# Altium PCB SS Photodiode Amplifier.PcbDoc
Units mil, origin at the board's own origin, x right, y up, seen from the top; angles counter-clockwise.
Board outline 2000 x 1500 mil, 2 copper layers (Top Layer, Bottom Layer), stack 62 mil thick; 19 components, 6 nets, 62 pads, 2 vias.
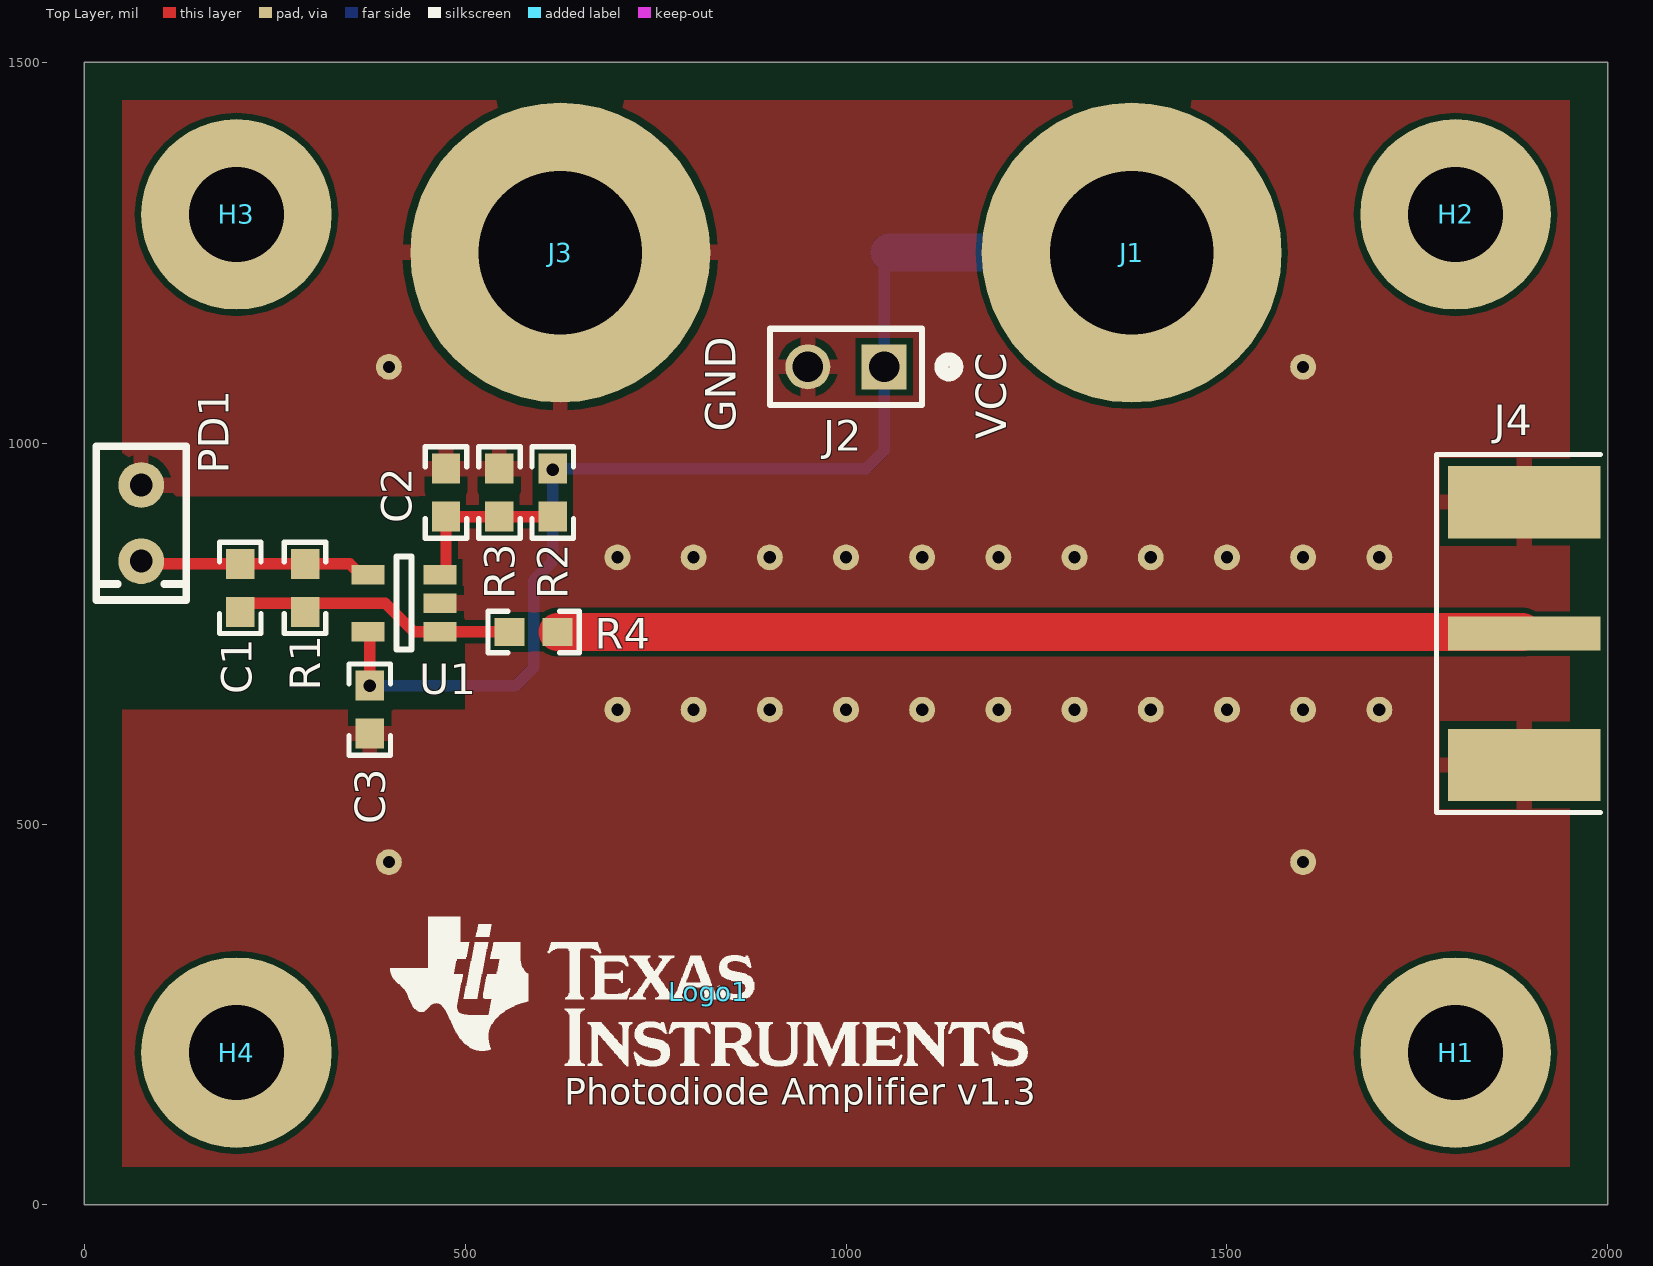
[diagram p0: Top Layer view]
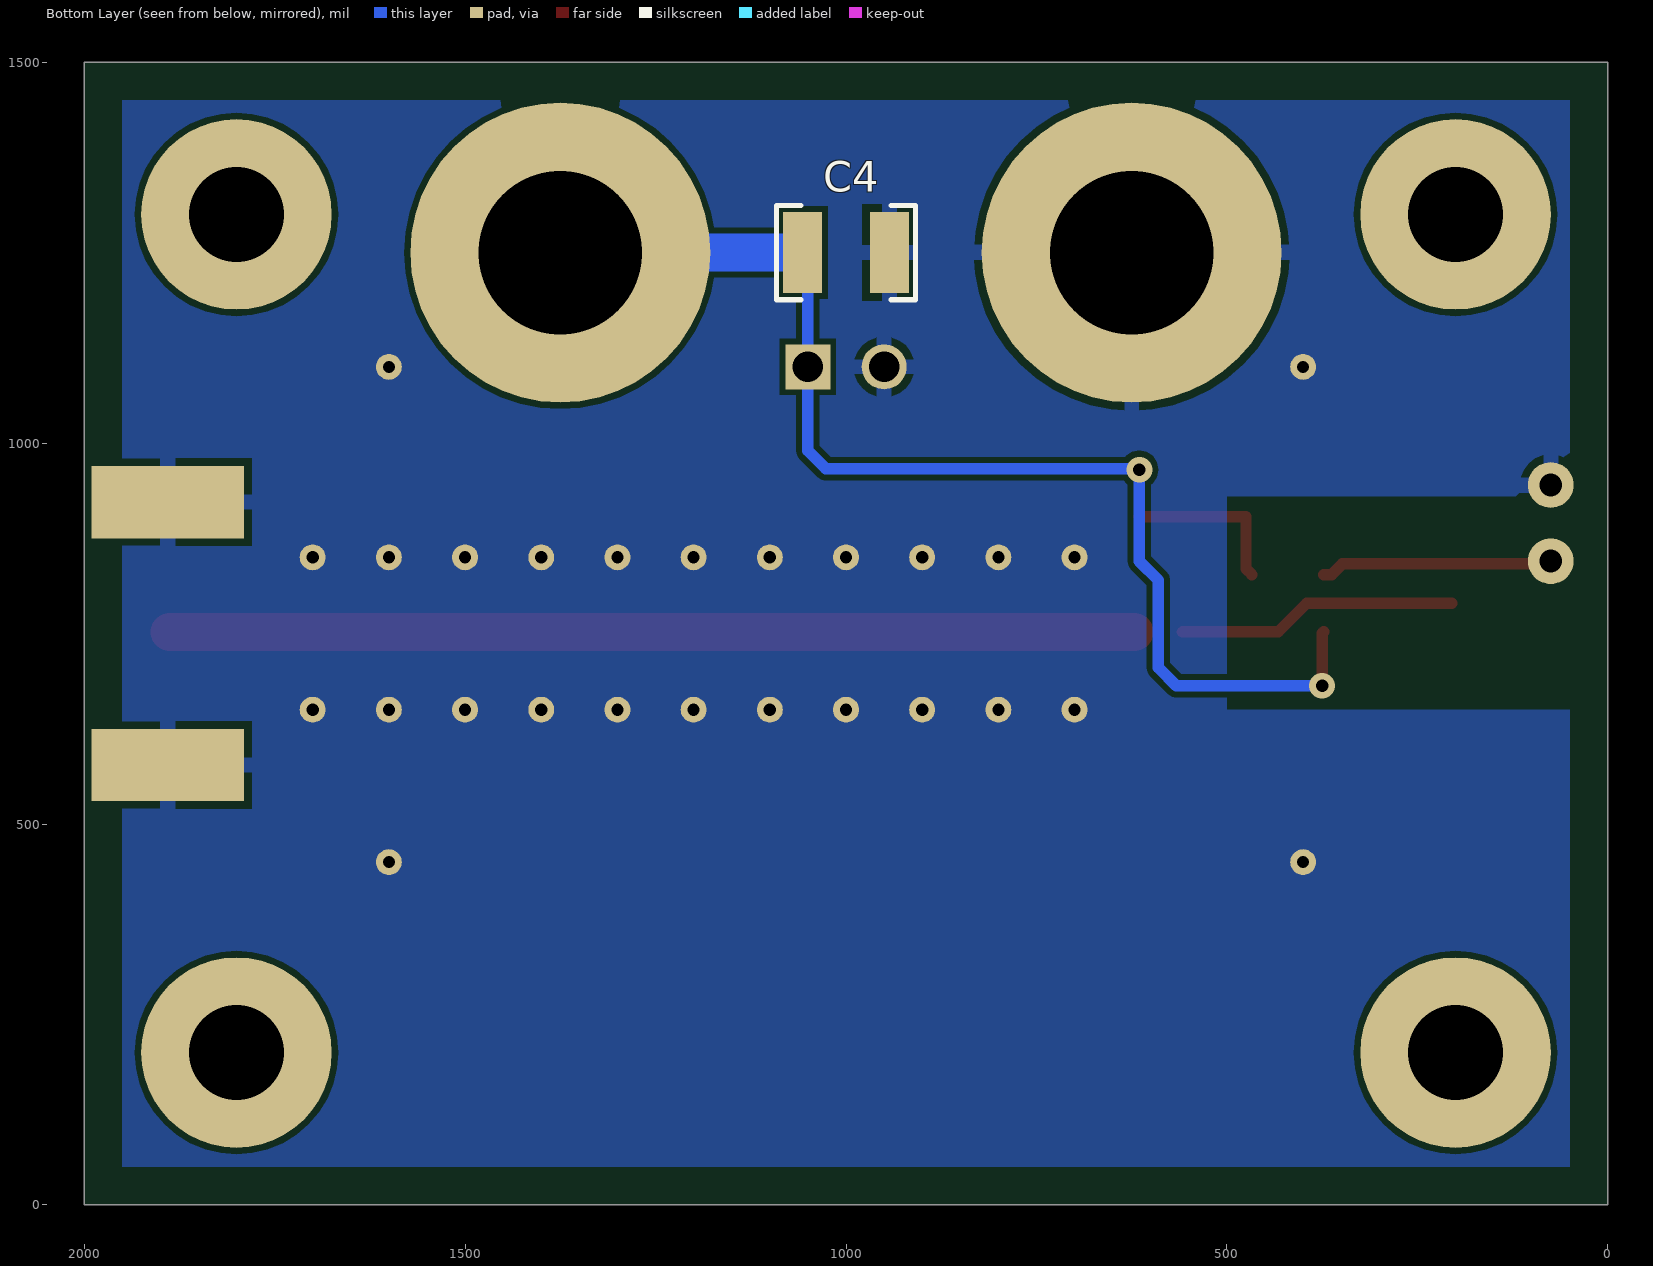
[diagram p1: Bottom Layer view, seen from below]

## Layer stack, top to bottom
Top Layer: signal copper 1.4
Dielectric: core 59.2, FR-4, Dk 4.8
Bottom Layer: signal copper 1.4

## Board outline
0,0 2000,0 2000,1500 0,1500

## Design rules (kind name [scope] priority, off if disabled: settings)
AcuteAngle [All] p1: minimum=4.50000000000000E+0001 checktracksonly=FALSE
AssemblyTestPointUsage [All] p1: valid=2
Clearance "Transmission Line Clearance" [InNet('NetJ4_1')] p1: gap=7
Clearance Clearance_BoardEdge_MountingHoles [OnCopper and InComponentClass('Mounting Holes') vs IsKeepOut] p2: gap=40
Clearance Clearance_BoardEdge_Poly [OnCopper and InPoly vs IsKeepOut] p3: gap=25
Clearance Clearance_BoardEdge [OnCopper and Not InComponentClass('Logo') and not InComponentClass('FiducialMark') and not InRegion(1000,500,4000,800) vs IsKeepOut] p4: gap=75
Clearance [All] p5: gap=8
ComponentClearance ComponentClearance_Logo [InComponentClass(Logo)] p1: gap=50 collisioncheckmode=3 verticalgap=10 showdistances=FALSE
ComponentClearance ComponentClearance_ScrewToNut [(HasFootprint('NY PMS 440 0025 PH')) vs (HasFootprint('Keystone_1902C'))] p2: gap=5 collisioncheckmode=3 verticalgap=10 showdistances=FALSE
ComponentClearance ComponentClearance_MountingHoles [InComponentClass('Mounting Holes')] p3: gap=250 collisioncheckmode=3 verticalgap=100000 showdistances=FALSE
ComponentClearance ComponentClearance_SmallPassives [HasFootprint('0201*') or HasFootprint('0402*') or HasFootprint('0508') or HasFootprint('0603*') or HasFootprint('0612') or HasFootprint('0805*') or HasFootprint('0815*') or HasFootprint('0830*') or HasFootprint('1206*') or HasFootprint('1210*') or HasFootprint('1808*') or HasFootprint('1812*') or HasFootprint('1825*') or HasFootprint('2010*') or HasFootprint('2220*') or HasFootprint('2225*') or HasFootprint('2512*') or HasFootprint('2728*') or HasFootprint('3518*') vs HasFootprint('0201*') or HasFootprint('0402*') or HasFootprint('0508') or HasFootprint('0603*') or HasFootprint('0612') or HasFootprint('0805*') or HasFootprint('0815*') or HasFootprint('0830*') or HasFootprint('1206*') or HasFootprint('1210*') or HasFootprint('1808*') or HasFootprint('1812*') or HasFootprint('1825*') or HasFootprint('2010*') or HasFootprint('2220*') or HasFootprint('2225*') or HasFootprint('2512*') or HasFootprint('2728*') or HasFootprint('3518*')] p4: gap=10 collisioncheckmode=3 verticalgap=10 showdistances=FALSE
ComponentClearance ComponentClearance_THtoSMT [IsThruComponent vs IsSMTComponent] p5: gap=10 collisioncheckmode=3 verticalgap=100000 showdistances=FALSE
ComponentClearance ComponentClearance_THtoTH [IsThruComponent vs IsThruComponent] p6: gap=10 collisioncheckmode=3 verticalgap=100000 showdistances=FALSE
ComponentClearance [All] p7: gap=40 collisioncheckmode=3 verticalgap=10 showdistances=FALSE
DiffPairsRouting [All] p1: maxlimit=100 minlimit=10 mostfreqgap=10 maxuncoupledlength=1000
FabricationTestPointUsage TestPointUsage [All] p1: valid=2 allowmultiple=FALSE
FabricationTestpoint Testpoint [All] p1: side=3 testpointundercomponent=TRUE minsize=40 maxsize=100 preferedsize=60 minholesize=0 maxholesize=40 preferedholesize=32 testpointgrid=1 allowsidetop=TRUE allowsidebottom=TRUE usegrid=TRUE gridtolerance=0.01
FanoutControl Fanout_LCC [IsLCC] p1: bgadir=Out bgaviamode=Centered fanoutstyle=Auto fanoutdirection=Alternating viagrid=1 // Fanout_LCC (Default Rule)
FanoutControl Fanout_BGA [IsBGA] p2: bgadir=Out bgaviamode=Centered fanoutstyle=Auto fanoutdirection=Alternating viagrid=1 // Fanout_BGA (Default Rule)
FanoutControl Fanout_Default [All] p4: bgadir=Out bgaviamode=Centered fanoutstyle=Auto fanoutdirection=Alternating viagrid=1 // Fanout_Default (Default Rule)
FanoutControl Fanout_Small [(CompPinCount < 5)] p5: bgadir=Out bgaviamode=Centered fanoutstyle=Auto fanoutdirection=OutThenIn viagrid=1 // Fanout_Small (Default Rule)
HoleSize [All] p1: absolutevalues=TRUE maxlimit=251 minlimit=8 maxpercent=80.000 minpercent=20.000
MinimumAnnularRing [All] p1: minimumring=9
MinimumSolderMaskSliver MinimumSolderMaskSliver_Logo [InComponentClass('Logo') vs InComponentClass('Logo')] p1: minsoldermaskwidth=0.7
MinimumSolderMaskSliver [All] p2: minsoldermaskwidth=4
PlaneConnect [All] p1: planeconnectstyle=Relief reliefexpansion=10 reliefentries=4 reliefconductorwidth=10 reliefairgap=10
PolygonConnect GNDVia [InPadClass('GNDVia')] p1: connectstyle=Direct reliefconductorwidth=10 reliefentries=4 polygonreliefangle="90 Angle" airgapwidth=10
PolygonConnect "SMA GND" [(InComponent('J1') AND InNet('GND'))] p2: connectstyle=Direct reliefconductorwidth=10 reliefentries=4 polygonreliefangle="90 Angle" airgapwidth=10
PolygonConnect [All] p3: connectstyle=Relief reliefconductorwidth=20 reliefentries=4 polygonreliefangle="90 Angle" airgapwidth=10
RoutingVias [All] p1: holewidth=16 width=34 viastyle="Through Hole" minholewidth=8 minwidth=26 maxholewidth=40 maxwidth=65
SMDToCorner [All] p1: distance=30000
SilkToSilkClearance [All] p1: silktosilkclearance=5
SilkscreenOverComponentPads [All] p1: minsilkscreentomaskgap=5
SolderMaskExpansion [All] p1: expansion=3
Width [All] p1: maxlimit=100 minlimit=6 preferedwidth=15 checkconnectedcopper=TRUE
14 further rules are at their usual default settings.

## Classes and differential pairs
component class Logo: Logo1
component class Header: J2
component class Schematic: C1 C2 C3 H1 H2 H3 H4 J1 J2 J3 Logo1 PD1 R1 R2 R3 R4 U1
pad class GNDVia: Free-0 Free-1 Free-2 Free-3 Free-4 Free-5 Free-6 Free-7 Free-8 Free-9 Free-10 Free-11 Free-12 Free-13 Free-14 Free-15 Free-16 Free-17 Free-18 Free-19 Free-20 Free-21 Free-22 Free-23 Free-24 Free-25

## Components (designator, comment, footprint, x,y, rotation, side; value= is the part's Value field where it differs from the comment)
C1 "06035A2R7CAT2A" 0603 205,810 r90 top
C2 "C0603C105K4PACTU" 0603 475,935 r90 top
C3 "0603YC104JAT2A" 0603 375,650 r90 top
C4 "C1210C106K8PACTU" 1210 1000,1250 r180 bottom
H1 "NA" "Mounting Hole" 1800,200 r0 top
H2 "NA" "Mounting Hole" 1800,1300 r0 top
H3 "NA" "Mounting Hole" 200,1300 r0 top
H4 "NA" "Mounting Hole" 200,200 r0 top
J1 "575-4" Keystone_575-4 1375,1250 r0 top
J2 "5-146261-1" CONN_5-146261-1 1000,1100 r180 top
J3 "575-4" Keystone_575-4 625,1250 r180 top
J4 "142-0701-851" Emerson_142-0701-851 1890,750 r270 top
Logo1 "Texas Instruments" TI_Stacked_Overlay_Small 820,280 r0 top
PD1 "PDB-C156" PDB-C156 75,895 r180 top
R1 "CRCW060353K6FKEA" 0603 290,810 r270 top
R2 "CRCW060310K0FKEA" 0603 615,935 r270 top
R3 "CRCW0603205RFKEA" 0603 545,935 r270 top
R4 "CRCW060349R9FKEA" 0603 590,752 r0 top
U1 "OPA322AIDBVR" DBV0005A_N 420,790 r180 top

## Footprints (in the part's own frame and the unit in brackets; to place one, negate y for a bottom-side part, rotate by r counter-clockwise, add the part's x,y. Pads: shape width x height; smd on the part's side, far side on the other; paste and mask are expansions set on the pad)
0603 [mm] "0603 from SM-752 data"
  rect 1x0.95 smd: 1(-0.8,0) 2(0.8,0)
  silkscreen extent -1.52,-0.69 1.52,0.69, body extent -0.87,-0.47 0.87,0.47, height 0.85
1210 [mm] "1210 from SM-752 data"
  rect 1.3x2.7 smd: 1(-1.45,0) 2(1.45,0)
  silkscreen extent -2.32,-1.57 2.32,1.57, body extent -1.7,-1.35 1.7,1.35, height 1.35
CONN_5-146261-1 [mm] "Sullins"
  rect 1.5x1.5 hole 1.02: 1(-1.27,0)
  round 1.5 hole 1.02: 2(1.27,0)
  silkscreen extent -3.68,-1.27 2.54,1.27, body extent -2.51,-1.27 2.51,1.27, height 10.87
DBV0005A_N [mm] "SOT23, 5-Leads, Body 2.9x1.6mm, Pitch 0.95mm, Lead Span 2.8mm, IPC Medium Density"
  rect 1.1x0.65 smd: 1(-1.2,0.95) 2(-1.2,0) 3(-1.2,-0.95) 4(1.2,-0.95) 5(1.2,0.95)
  silkscreen extent -0.25,-1.55 0.25,1.55, body extent -1.42,-1.46 1.42,1.46, height 1.08
Emerson_142-0701-851 [mil] "Johnson Components"
  rect 45x200 smd: 1(0,0)
  rect 95x200 smd: 2(-172.5,0) 3(172.5,0)
  rect 95x200 smd far side: 4(172.5,0) 5(-172.5,0)
  silkscreen extent -235,-115 235,100, body extent -190,-95 190,487, height 155
Keystone_575-4 [mm] "Banana Jack"
  round 10 hole 5.45: 1(0,0)
  body extent -3.95,-3.95 3.92,3.93, height 2.36
"Mounting Hole" [mil]
  round 250 hole 125: 1(0,0)
PDB-C156 [mil] "Photodiode"
  round 60 hole 30: 1(0,50) 2(0,-50)
  silkscreen extent -59,-101 59,101
TI_Stacked_Overlay_Small [mil]
  silkscreen extent -418,-98 418,98

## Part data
C1: "CAP, CERM, 2.7pF, 50V, +/-9%, C0G/NP0, 0603"
C2: "CAP, CERM, 1uF, 16V, +/-10%, X5R, 0603"
C3: "CAP, CERM, 0.1uF, 16V, +/-5%, X7R, 0603"
C4: "CAP, CERM, 10uF, 10V, +/-10%, X5R, 1210"
H1 H2 H3 H4: library part "Mounting Hole", "Mounting Hole"
J1 J3: "Standard Banana Jack, Uninsulated, 5.5mm"
J2: "Header, 100mil, 2x1, Gold, TH"
J4: "Connector, SMT, End launch SMA 50 ohm"
Logo1: library part TI_Logo, "Texas Instrument Corporate Signature"
PD1: "Photodiode"
R1: "RES, 53.6k ohm, 1%, 0.1W, 0603"
R2: "RES, 10.0k ohm, 1%, 0.1W, 0603"
R3: "RES, 205 ohm, 1%, 0.1W, 0603"
R4: "RES, 49.9 ohm, 1%, 0.1W, 0603"
U1: "20 MHz, Low Noise, RRIO, CMOS Operational Amplifier with Shutdown, 1.8 to 5.5 V, -40 to 125 degC, 5-pin SOT23 (DBV0005A), Green (RoHS & no Sb/Br)"

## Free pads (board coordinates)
  round 34 hole 16: 0(700,850) 1(800,850) 2(900,850) 3(1000,850) 4(1100,850) 5(1200,850) 6(1300,850) 7(1400,850) 8(1500,850) 9(1600,850) 10(1700,850) 11(1700,650) 12(1600,650) 13(1500,650) 14(1400,650) 15(1300,650) 16(1200,650) 17(1100,650) 18(1000,650) 19(900,650) 20(800,650) 21(700,650) 22(400,1100) 23(400,450) 24(1600,450) 25(1600,1100)

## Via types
v1: diameter 34, hole 16, Top Layer to Bottom Layer, 2 vias

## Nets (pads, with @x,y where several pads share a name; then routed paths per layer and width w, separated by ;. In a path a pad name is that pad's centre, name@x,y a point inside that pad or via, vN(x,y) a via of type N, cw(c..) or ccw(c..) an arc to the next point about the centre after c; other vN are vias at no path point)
GND: C2.2 C3.1 C4.2 J2.2 J3.1 J4.2 J4.3 J4.4 J4.5 pad.0 pad.1 pad.2 pad.3 pad.4 pad.5 pad.6 pad.7 pad.8 pad.9 pad.10 pad.11 pad.12 pad.13 pad.14 pad.15 pad.16 pad.17 pad.18 pad.19 pad.20 pad.21 pad.22 pad.23 pad.24 pad.25 PD1.2 R3.1 U1.2
NetC1_1: C1.1 R1.2 R4.1 U1.1 | length 369.2
  Top Layer w15: C1.1@205,790 395,790 432.4,752.6 U1.1 557.91,752.6 R4.1
NetC1_2: C1.2 PD1.1 R1.1 U1.4 | length 299.2
  Top Layer w15: PD1.1@80,840 81.5,841.5 R1.1 348.5,841.5 362.6,827.4 U1.4
NetC2_1: C2.1 R2.2 R3.2 U1.3 | length 219.3
  Top Layer w15: U1.3 475,835.16 C2.1 R2.2
NetJ4_1: J4.1 R4.2 | length 1269.3
  Top Layer w15: J4.1@1888,752 J4.1
  Top Layer w50: R4.2 J4.1@1888,752
VCC: C3.2 C4.1 J1.1 J2.1 R2.1 U1.5 | length 1594.2
  Top Layer w15: U1.5 375,750.35 v1(375,681.5)
  Bottom Layer w15: v1(375,681.5) 566.5,681.5 590,705 590,820 615,845 615,966.5 1026.5,966.5 1050,990 J2.1 1050,1242.91 C4.1
  Bottom Layer w50: C4.1 J1.1
  other v1: 615,965
pads on no net: H1.1 H2.1 H3.1 H4.1

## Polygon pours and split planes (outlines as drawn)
GND on Top Layer "Top Layer GND" (solid, pour order 4): 50,1450 50,50 1950,50 1950,1450
GND on Bottom Layer "Bottom Layer GND" (solid, pour order 3): 50,1450 50,50 1950,50 1950,1450

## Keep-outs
Keep-Out Layer:
  lines w10: -5,3450 cw(c0,3450) 0,3455 ; -5,3450 cw(c0,3450) 0,3455 ; -5,3450 cw(c0,3450) 0,3455 ; -5,3450 cw(c0,3450) 0,3455 ; -5,3450 cw(c0,3450) 0,3455 ; -5,3450 cw(c0,3450) 0,3455 ; 4950,-5 ccw(c4950,0) 4955,0 ; 4950,-5 ccw(c4950,0) 4955,0 ; 4950,-5 ccw(c4950,0) 4955,0 ; 4950,-5 ccw(c4950,0) 4955,0 ; 4950,-5 ccw(c4950,0) 4955,0 ; 4950,-5 ccw(c4950,0) 4955,0 ; 4950,3455 cw(c4950,3450) 4955,3450 ; 4950,3455 cw(c4950,3450) 4955,3450 ; 4950,3455 cw(c4950,3450) 4955,3450 ; 4950,3455 cw(c4950,3450) 4955,3450 ; 4950,3455 cw(c4950,3450) 4955,3450 ; 4950,3455 cw(c4950,3450) 4955,3450
  text ".Layer_Name" at 577,-858.49 h60

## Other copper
Top Layer:
  pour cut-out: 20,930 20,650 500,650 500,770 440,770 440,930
Bottom Layer:
  pour cut-out: 20,930 20,650 500,650 500,930

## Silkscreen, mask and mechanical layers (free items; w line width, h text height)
Top Overlay:
  text "GND" at 855,1015 h40 r90
  text "VCC" at 1210,1005 h40 r90
  text "Photodiode Amplifier v1.3" at 630,120 h60
Top Paste:
  text ".Layer_Name" at 577,-858.49 h60
Bottom Paste:
  text ".Layer_Name" at 577,-858.49 h60
Drill Guide:
  text ".Layer_Name" at 577,-858.49 h60
M1 Board Outline:
  the board outline again, w10
M2 Board Dimensions:
  rectangle: 124.5,-410.5 499.5,-285.5
  rectangle: -0.5,-285.5 124.5,-160.5
  lines w7: -0.5,-285.5 999.5,-285.5 ; 124.5,-410.5 124.5,-160.5 ; 249.5,-410.5 249.5,-160.5 ; 499.5,-410.5 499.5,-160.5 ; 749.5,-410.5 749.5,-160.5 ; -0.5,-410.5 -0.5,-160.5 999.5,-160.5 999.5,-410.5 -0.5,-410.5
  lines w10: -0.5,-475.5 -0.5,-455.5 ; 59.5,-485.5 -0.5,-465.5 ; 59.5,-445.5 -0.5,-465.5 ; 223.58,-465.5 -0.5,-465.5 ; 775.42,-465.5 999.5,-465.5 ; 939.5,-485.5 999.5,-465.5 ; 939.5,-445.5 999.5,-465.5 ; 999.5,-475.5 999.5,-455.5
  text "1000 (mil)" at 233.58,-501.49 h60
  text ".Layer_Name" at 577,-858.49 h60
M3 3D STEP Top:
  text ".Layer_Name" at 577,-858.49 h60
M4 3D STEP Bottom:
  text ".Layer_Name" at 577,-858.49 h60
M5 Assembly Top:
  lines w7: 4210,929.26 5335,929.26 ; 4210,1051.76 5332.5,1051.76 ; 4910,1171.76 4210,1171.76 5335,1171.76 ; 5139,353 5139,-9.5 ; 5454,-9.5 5454,353 ; 5839,-9.5 5139,-9.5 ; 6264,353 6264,-9.5 5139,-9.5
  lines w10: -292,-930.17 6308,-930.17 ; -292,-726.83 6310,-726.83 ; -292,-523.5 -292,-1133.5 3713,-1133.5 6310,-1133.5 6310,-523.5 -291.5,-523.5 -291.5,-1133.5 1284,-1133.5 ; 2173,-1133.5 2173,-523.5 ; 3440,-726.83 3440,-523.5 ; 4280,-726.83 4280,-523.5 ; 4902,-1140 4902,-937.17
  text "TABLE 1" at 4597.5,1206.76 h40
  text "Label text" at 4662,1112 h40
  text "Variant" at 4235,1096.76 h40
  text "001" at 4302.5,976.76 h40
  text "ChangeMe!" at 4580,974.26 h40
  text "002" at 4302.5,851.76 h40
  text "ChangeMe!" at 4575,849.26 h40
  text "COMPONENTS MARKED 'DNP' SHOULD NOT BE POPULATED, AND MAY NOT BE IN BILL OF MATERIALS" at 1153.5,-318.5 h60
  text "ASSEMBLY VARIANT:" at 1153,-434 h60
  text ".VariantName" at 2189,-434 h60
  text "PCB VIEWED FROM TOP SIDE" at -228.5,-655.67 h60
  text "BOARD #:" at 2248,-655.67 h60
  text ".PRJ_Number" at 2793.5,-655.67 h60
  text "REV:" at 3638,-655.67 h60
  text ".PCB_Rev" at 3929.5,-655.67 h60
  text "SVN REV:" at 4476,-655.67 h60
  text ".VersionControl_RevNumber" at 4982,-655.67 h60
  text "IGNORE ->" at -228.5,-858.49 h60
  text "PLOT NAME =" at -228.5,-1064.34 h60
  text ".plot_File_Name" at 577,-1064.34 h60
  text "GENERATED    :" at 2250,-1064.34 h60
  text ".Print_Date" at 3119.5,-1064.34 h60
  text ".Print_Time" at 3848.5,-1064.34 h60
  text "TEXAS INSTRUMENTS" at 5113,-1064.34 h60
M6 Assembly Bottom:
  lines w10: -292.5,-727.33 6309.5,-727.33 ; -290.5,-930.67 6309.5,-930.67 ; 1115.5,-1140.5 1115.5,-937.67 ; 1737.5,-727.33 1737.5,-524 ; 2577.5,-727.33 2577.5,-524 ; 3844.5,-1134 3844.5,-524 ; 4733.5,-1134 6309,-1134 6309,-524 -292.5,-524 -292.5,-1134 2304.5,-1134 6309.5,-1134 6309.5,-524
  text "COMPONENTS MARKED 'DNP' SHOULD NOT BE POPULATED, AND MAY NOT BE IN BILL OF MATERIALS" at 6102,-318 h60
  text ".VariantName" at 5058,-434 h60
  text "ASSEMBLY VARIANT:" at 6097,-434 h60
  text ".VersionControl_RevNumber" at 1035.5,-656.17 h60
  text "SVN REV:" at 1541.5,-656.17 h60
  text ".PCB_Rev" at 2088,-656.17 h60
  text "REV:" at 2379.5,-656.17 h60
  text ".PRJ_Number" at 3224,-656.17 h60
  text "BOARD #:" at 3769.5,-656.17 h60
  text "PCB VIEWED FROM BOTTOM SIDE" at 6246,-656.17 h60
  text "IGNORE ->" at 2547.85,-858.49 h60
  text "TEXAS INSTRUMENTS" at 904.5,-1064.84 h60
  text ".Print_Time" at 2169,-1064.84 h60
  text ".Print_Date" at 2898,-1064.84 h60
  text "GENERATED    :" at 3767.5,-1064.84 h60
  text ".plot_File_Name" at 5440.5,-1064.84 h60
  text "PLOT NAME =" at 6246,-1064.84 h60
M9 Title Sheet:
  drawing of 57 lines, arcs and shapes, not listed
  text "1" at 739.84,8036.5 h70
  text "2" at 3235.5,8036.5 h70
  text "3" at 5724.84,8036.5 h70
  text "4" at 8231.51,8036.5 h70
  text "5" at 10730.5,8036.5 h70
  text "6" at 13235.5,8036.5 h70
  text "A" at -416.5,6893.5 h70
  text "A" at 14383.5,6893.5 h70
  text "B" at -416.5,4513.5 h70
  text "B" at 14383.5,4513.5 h70
  text "C" at -416.5,2138.5 h70
  text "C" at 14383.5,2138.5 h70
  text "PROJECT TITLE:" at 11343.5,277.5 h45
  text ".PRJ_Title" at 11393.5,144.17 h70
  text "DESIGNED FOR:" at 11343.5,-23.5 h45
  text ".PRJ_Customer" at 11393.5,-163.5 h70
  text "D" at -416.5,-231.5 h70
  text "D" at 14383.5,-231.5 h70
  text "FILE NAME:" at 11343.5,-323.5 h45
  text ".PCB_File_Name_No_Path" at 11393.5,-443.5 h70
  text "Texas Instruments (TI) and/or its licensors do not warrant the accuracy or completeness of this specification" at 6374,-605.34 h45
  text "ENGINEER:" at 11343.5,-613.5 h45
  text "LAYOUT BY:" at 12848.5,-613.5 h45
  text "or any information contained therein. TI and/or its licensors do not warrant that this design will meet" at 6329.01,-718 h45
  text ".PRJ_Engineer" at 11393.5,-768.49 h70
  text ".PCB_Layout" at 12899,-768.49 h70
  text "the specifications, will be suitable for your application or fit for any particular purpose, or will operate in" at 6329.01,-830.67 h45
  text ".Layer_Name" at 577,-858.49 h60
  text "ALTIUM DESIGNER VERSION:" at 12848.5,-923.5 h45
  text "an implementation. TI and/or its licensors do not warrant that the design is production worthy. You should" at 6329.01,-943.33 h45
  text "completely validate and test your design implementation to confirm the system functionality for your application." at 6374,-1056 h45
  text ".print_Scale" at 11393.5,-1056.83 h70
  text ".Application_BuildNumber" at 12899,-1056.83 h70
  text "1" at 739.84,-1263.5 h70
  text "2" at 3235.5,-1263.5 h70
  text "3" at 5724.84,-1263.5 h70
  text "4" at 8231.51,-1263.5 h70
  text "5" at 10730.5,-1263.5 h70
  text "6" at 13235.5,-1263.5 h70
M10 Fab Notes:
  drawing of 203 lines, arcs and shapes, not listed
  text "DESIGN INFORMATION" at 12381.02,6810 h60
  text "(REFER ALSO ARRAY/PANEL PROFILING INFORMATION)" at 12019.46,6648.29 h60
  text "BOARD SIZE" at 11333.46,6644 h60
  text "3450MIL" at 11795.78,6516.18 h60
  text "X" at 12301.46,6516.18 h60
  text "4950MIL" at 12532.78,6516.18 h60
  text "Number of Layers :" at 11736.46,6319 h60
  text "2" at 12831.27,6309 h60
  text "MIN. TRACK WIDTH:" at 11736.46,6180 h60
  text "8" at 12832.7,6180 h60
  text "MIL" at 12987.46,6180 h60
  text "MIN. CLEARANCE:" at 11736.46,6048 h60
  text "8" at 12832.7,6048 h60
  text "MIL" at 12987.46,6048 h60
  text "MIN. VIA PAD SIZE:" at 11736.46,5916 h60
  text "24" at 12802.71,5916 h60
  text "MIL" at 12987.46,5916 h60
  text "0.05mm (2MIL)" at 12431.46,5774.29 h60
  text "MINIMUM ANNULAR RING" at 11407.23,5770 h60
  text "EXTERNAL" at 13139.46,5770 h60
  text "PER" at 11607.23,5652 h60
  text "IPC-D-275 CLASS 2 LEVEL C" at 11827.23,5652 h60
  text "MIL, HOLES" at 13315.46,5539.71 h60
  text "+/-" at 12923,5539 h60
  text "+/-" at 13777,5539 h60
  text "REGISTRATION TOLERANCES:" at 11407.23,5534 h60
  text "METAL" at 12607,5534 h60
  text "5" at 13183.2,5534 h60
  text "3" at 14016.2,5534 h60
  text "MIL" at 14132.46,5534 h60
  text "MATERIAL:" at 11332.46,5324.54 h60
  text "FR-4 High Tg" at 12318.9,5184.21 h60
  text "FR-4" at 11793.46,5175.64 h60
  text "X" at 12165.46,5175.64 h60
  text "OTHER" at 13241.46,5175.64 h60
  text "62 MIL (1.6mm) +/-10%" at 12073.56,5012.92 h60
  text "THICKNESS:" at 11407.23,5008.64 h60
  text "X" at 11945.4,5008.64 h60
  text "OTHER" at 13358.46,5008.64 h60
  text "TOLERANCE:" at 11407.23,4850.64 h60
  text "X" at 12246.53,4850.64 h60
  text "ANSI IPC-6012 TYPE 3 CLASS 2" at 12433.48,4850.64 h60
  text "OTHER +/-" at 12433.46,4694.64 h60
  text "BOW & TWIST:" at 11407.23,4537.64 h60
  text "X" at 12246.53,4537.64 h60
  text "ANSI IPC-6012 TYPE 3 CLASS 2" at 12433.48,4537.64 h60
  text "OTHER +/-" at 12433.46,4379.13 h60
  text "COPPER THICKNESS (FINISHED):" at 11332.46,4243.64 h60
  text "1.4MIL (1oz)" at 12212.46,4090.92 h60
  text "2MIL (1.4oz)" at 12979.46,4090.92 h60
  text "2.8MIL (2oz)" at 13706.46,4090.92 h60
  text "OUTER:" at 11689.46,4086.64 h60
  text "X" at 12084,4086 h60
  text "1.4MIL (1oz)" at 12562.46,3933.92 h60
  text "2.8MIL (2oz)" at 13406.46,3933.92 h60
  text "INNER SIGNAL:" at 11689.46,3929.64 h60
  text "X" at 12435.42,3929.64 h60
  text "DRILLING:" at 11332.46,3790.64 h60
  text "REFERENCE:" at 11407.23,3673.64 h60
  text "X" at 12055.46,3673.64 h60
  text "AS SHOWN" at 12242.46,3673.64 h60
  text "X" at 12956.46,3673.64 h60
  text "NC_DRILL FILES" at 13093.46,3673.64 h60
  text "PTH MIN COPPER THICKNESS:" at 11407.23,3515.64 h60
  text "X" at 12757.46,3515.64 h60
  text "1MIL" at 12894.46,3515.64 h60
  text "OTHER" at 13391.46,3515.64 h60
  text "BOARD FINISH:" at 11332.46,3356.64 h60
  text "SILKSCREEN:" at 11487.68,3238.64 h60
  text "X" at 12436.46,3238.64 h60
  text "TOP" at 12562.46,3238.64 h60
  text "X" at 12946.46,3238.64 h60
  text "BOTTOM" at 13073.46,3238.64 h60
  text "SILKSCREEN COLOR:" at 11487.68,3071.64 h60
  text "X" at 12435.42,3071.64 h60
  text "WHITE" at 12562.46,3071.64 h60
  text "OTHER" at 13073.46,3071.64 h60
  text "SOLDER RESIST COLOR:" at 11487.68,2901.64 h60
  text "X" at 12055.42,2742.44 h60
  text "GREEN" at 12182.46,2742.44 h60
  text "BLUE" at 12773.46,2742.44 h60
  text "OTHER" at 13311.46,2742.44 h60
  text "IMMERSION GOLD (ENIG)" at 12393.46,2553.92 h60
  text "SURFACE FINISH:" at 11332.46,2549.64 h60
  text "X" at 12206.51,2549.64 h60
  text "Pb-FREE HASL" at 13625.75,2549.64 h60
  text "OTHER" at 12393.46,2392.64 h60
  text "ARRAY/PANEL:" at 11332.46,2213.64 h60
  text "CUT AND TRIM PER MECH LAYER 1" at 12393.46,2209.35 h60
  text "N.C. ROUTE" at 12393.46,2057.64 h60
  text "X" at 13072.46,2057.64 h60
  text "V. SCORE" at 13259.46,2057.64 h60
  text "CERTIFICATION:" at 11332.46,1920.64 h60
  text "MATERIALS AND WORKMANSHIP FOR ALL PCBS" at 12057.46,1920.64 h60
  text "TO MEET OR EXCEED THE REQUIREMENTS OF:" at 12057.46,1822.64 h60
  text "X" at 11683.96,1686.13 h60
  text "ANSI IPC-A-600F CLASS ->" at 11822.96,1686.13 h60
  text "X" at 13462.02,1686.13 h60
  text "2" at 13580.96,1686.14 h60
  text "1" at 13265.96,1684.64 h60
  text "3" at 13934.96,1684.64 h60
  text "X" at 11686.02,1526.64 h60
  text "UL 94V-0" at 11822.96,1526.64 h60
  text "X" at 12498.02,1526.64 h60
  text "RoHS" at 12634.96,1526.64 h60
  text "OTHER" at 13279.36,1526.64 h60
  text "PER ORDER" at 13676.42,1526.64 h60
  text "ADDITIONAL REQUIREMENTS:" at 11332.46,1385.64 h60
  text "MICROSECTION:" at 11407.23,1270.64 h60
  text "YES" at 12312.96,1270.64 h60
  text "REQUIRED" at 13174.46,1114.49 h60
  text "BARE BOARD ELEC. TEST:" at 11407.23,1111.64 h60
  text "NONE" at 12712.96,1111.64 h60
  text "X" at 13047.46,1111.64 h60
  text "PER ORDER" at 13766.46,1111.64 h60
  text "MANUFACTURER'S ID/LOGO:" at 11407.23,954.64 h60
  text "RAIL" at 12872.96,950.35 h60
  text "X" at 13247.46,950.35 h60
  text "METAL" at 13364.77,950.35 h60
  text "SILK" at 13876.46,950.35 h60
  text ".Layer_Name" at 577,-858.49 h60
M11 Gerber Information:
  lines w10: -292,-930.17 6308,-930.17 ; -292,-726.83 6310,-726.83 ; -292,-523.5 -292,-1133.5 3713,-1133.5 6310,-1133.5 6310,-523.5 -291.5,-523.5 -291.5,-1133.5 1284,-1133.5 ; 2173,-1133.5 2173,-523.5 ; 3440,-726.83 3440,-523.5 ; 4280,-726.83 4280,-523.5 ; 4902,-1140 4902,-937.17
  text "ALL ARTWORK VIEWED FROM TOP SIDE" at -228.5,-655.67 h60
  text "BOARD #:" at 2248,-655.67 h60
  text ".PRJ_Number" at 2793.5,-655.67 h60
  text "REV:" at 3638,-655.67 h60
  text ".PCB_Rev" at 3929.5,-655.67 h60
  text "SVN REV:" at 4476,-655.67 h60
  text ".VersionControl_RevNumber" at 4982,-655.67 h60
  text "LAYER NAME =" at -228.5,-858.49 h60
  text "PLOT NAME =" at -228.5,-1064.34 h60
  text ".plot_File_Name" at 577,-1064.34 h60
  text "GENERATED    :" at 2250,-1064.34 h60
  text ".Print_Date" at 3119.5,-1064.34 h60
  text ".Print_Time" at 3848.5,-1064.34 h60
  text "TEXAS INSTRUMENTS" at 5113,-1064.34 h60
M12 Stackup:
  lines w6: 11360,7460 13910,7460 ; 11360,7564.4 13910,7564.4 ; 11300,6975 ccw(c11334,6975) 11334,6941 13936,6941 ccw(c13936,6975) 13970,6975 13970,7681 ccw(c13936,7681) 13936,7715 11334,7715 ccw(c11334,7681) 11300,7681 11300,6975
  text "The Stackup Legend below this is static." at 11605.5,7874.5 h60
  text "If you change the stackup, update the Legend." at 11615.5,7784.5 h60
  text "Layer Stack Up Detail for: Ref_Design.PcbDoc" at 11360,7597.1 h57
  text "Layer" at 11360,7525.4 h24
  text "Gerber" at 12255.81,7525.4 h24
  text "Copper" at 12819.33,7525.4 h24
  text "Dielectric" at 13422.04,7525.4 h24
  text "Name" at 11360,7477.4 h24
  text "Document" at 12255.81,7477.4 h24
  text "Thickness" at 12819.33,7477.4 h24
  text "Material" at 13422.04,7477.4 h24
  text "Top Solder Mask" at 11360,7384.44 h34
  text "(.GTS)" at 12255.81,7384.44 h34
  text "Solder Resist" at 13422.04,7384.44 h34
  text "Top Layer" at 11360,7287.69 h34
  text "(.GTL)" at 12255.81,7287.69 h34
  text "1.4mil" at 12819.33,7287.69 h34
  text "FR-4" at 13422.04,7239.31 h34
  text "Bottom Layer" at 11360,7190.94 h34
  text "(.GBL)" at 12255.81,7190.94 h34
  text "1.4mil" at 12819.33,7190.94 h34
  text "Bottom Solder Mask" at 11360,7094.19 h34
  text "(.GBS)" at 12255.81,7094.19 h34
  text "Solder Resist" at 13422.04,7094.19 h34
  text ".Layer_Name" at 577,-858.49 h60
M13 Component Bodies Top:
  text ".Layer_Name" at 577,-858.49 h60
M14 Component Bodies Bottom:
  text ".Layer_Name" at 577,-858.49 h60
M15 Courtyards Top:
  text ".Layer_Name" at 577,-858.49 h60
M16 Courtyards Bottom:
  text ".Layer_Name" at 577,-858.49 h60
